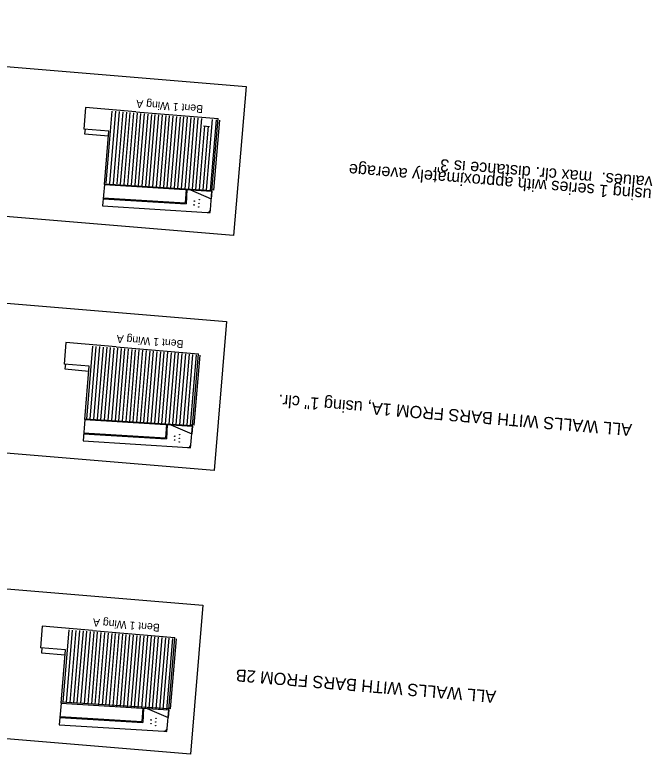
# Model space of a CAD drawing. Extents: x 1313815 to 1314857, y 2089008 to 2089414.
# Drawn here: x 1314659 to 1314747.7, y 2089292.2 to 2089395.1 of the extents above; entities that cross this region are included whole.
import ezdxf

# ---------------------------------------------------------------- set-up
doc = ezdxf.new("R2010")
doc.units = 0
for name, color, linetype in [('B-Gen-Construction Line', 7, 'Continuous'), ('B-Gen-Hidden', 7, 'Continuous'), ('B-Gen-Rebar', 7, 'Continuous'), ('B-Gen-Viewport', 7, 'Continuous'), ('B-Sub-Abutment Cap (Hidden)', 7, 'Continuous'), ('B-Sub-Wingwall', 7, 'Continuous'), ('B-Super-Parapet', 7, 'Continuous')]:
    doc.layers.add(name, color=color, linetype=linetype)

msp = doc.modelspace()

# ---------------------------------------------------------------- linework, layer by layer
at = {"layer": 'B-Gen-Construction Line'}
msp.add_line((1314685.25, 2089379.66), (1314686.06, 2089379.59), dxfattribs=at)
at = {"layer": 'B-Gen-Hidden'}
for p, q in [((1314686.69, 2089370.71), (1314687.5, 2089380.47)), ((1314671.45, 2089371.5), (1314686.42, 2089370.57)), ((1314671.46, 2089371.58), (1314686.43, 2089370.65)), ((1314682.81, 2089370.8), (1314682.69, 2089368.93)), ((1314682.93, 2089370.79), (1314682.81, 2089368.79)), ((1314683.43, 2089370.76), (1314686.33, 2089369.49)), ((1314686.69, 2089370.71), (1314686.19, 2089370.75)), ((1314671.28, 2089369.51), (1314682.81, 2089368.79)), ((1314671.29, 2089369.63), (1314682.69, 2089368.93)), ((1314686.17, 2089367.58), (1314686.21, 2089367.99)), ((1314685.77, 2089367.61), (1314686.17, 2089367.58)), ((1314683.96, 2089338), (1314684.77, 2089347.76)), ((1314668.72, 2089338.79), (1314683.69, 2089337.86)), ((1314668.73, 2089338.87), (1314683.7, 2089337.95)), ((1314680.08, 2089338.09), (1314679.96, 2089336.22)), ((1314680.2, 2089338.08), (1314680.08, 2089336.08)), ((1314680.7, 2089338.05), (1314683.6, 2089336.78)), ((1314683.96, 2089338), (1314683.46, 2089338.04)), ((1314668.56, 2089336.92), (1314679.96, 2089336.22)), ((1314668.55, 2089336.8), (1314680.08, 2089336.08)), ((1314683.04, 2089334.9), (1314683.44, 2089334.87)), ((1314683.44, 2089334.87), (1314683.48, 2089335.28)), ((1314680.66, 2089298.52), (1314681.48, 2089308.28)), ((1314665.42, 2089299.31), (1314680.4, 2089298.38)), ((1314665.44, 2089299.48), (1314680.41, 2089298.55)), ((1314676.78, 2089298.61), (1314676.66, 2089296.74)), ((1314676.9, 2089298.6), (1314676.78, 2089296.61)), ((1314677.4, 2089298.57), (1314680.31, 2089297.3)), ((1314680.66, 2089298.52), (1314680.16, 2089298.57)), ((1314665.26, 2089297.32), (1314676.78, 2089296.61)), ((1314665.27, 2089297.44), (1314676.66, 2089296.74)), ((1314680.15, 2089295.39), (1314680.18, 2089295.8)), ((1314679.74, 2089295.42), (1314680.15, 2089295.39))]:
    msp.add_line(p, q, dxfattribs=at)
at = {"layer": 'B-Gen-Rebar'}
for p, q in [((1314671.71, 2089371.67), (1314672.55, 2089381.72)), ((1314672.21, 2089371.64), (1314673.05, 2089381.68)), ((1314672.71, 2089371.6), (1314673.55, 2089381.64)), ((1314673.21, 2089371.57), (1314674.05, 2089381.59)), ((1314673.71, 2089371.53), (1314674.55, 2089381.55)), ((1314674.21, 2089371.5), (1314675.05, 2089381.51)), ((1314674.71, 2089371.46), (1314675.54, 2089381.47)), ((1314675.21, 2089371.43), (1314676.04, 2089381.43)), ((1314675.71, 2089371.39), (1314676.54, 2089381.39)), ((1314676.2, 2089371.36), (1314677.04, 2089381.34)), ((1314676.7, 2089371.33), (1314677.54, 2089381.3)), ((1314677.2, 2089371.29), (1314678.03, 2089381.26)), ((1314677.7, 2089371.26), (1314678.53, 2089381.22)), ((1314678.2, 2089371.22), (1314679.03, 2089381.18)), ((1314678.7, 2089371.19), (1314679.53, 2089381.14)), ((1314679.2, 2089371.15), (1314680.03, 2089381.09)), ((1314679.7, 2089371.12), (1314680.53, 2089381.05)), ((1314680.2, 2089371.08), (1314681.02, 2089381.01)), ((1314680.69, 2089371.05), (1314681.52, 2089380.97)), ((1314681.19, 2089371.02), (1314682.02, 2089380.93)), ((1314681.69, 2089370.98), (1314682.52, 2089380.89)), ((1314682.19, 2089370.95), (1314683.02, 2089380.85)), ((1314682.69, 2089370.91), (1314683.52, 2089380.8)), ((1314683.19, 2089370.88), (1314684.01, 2089380.76)), ((1314683.69, 2089370.84), (1314684.51, 2089380.72)), ((1314684.19, 2089370.81), (1314685.01, 2089380.68)), ((1314685.68, 2089370.71), (1314686.51, 2089380.55)), ((1314687, 2089380.51), (1314686.18, 2089370.67)), ((1314684.69, 2089370.77), (1314685.43, 2089379.64)), ((1314685.18, 2089370.74), (1314685.92, 2089379.6)), ((1314668.98, 2089338.86), (1314669.82, 2089349.01)), ((1314669.48, 2089338.83), (1314670.32, 2089348.97)), ((1314669.97, 2089338.8), (1314670.82, 2089348.93)), ((1314670.47, 2089338.77), (1314671.32, 2089348.88)), ((1314670.97, 2089338.74), (1314671.82, 2089348.84)), ((1314671.47, 2089338.7), (1314672.31, 2089348.8)), ((1314671.97, 2089338.67), (1314672.81, 2089348.76)), ((1314672.47, 2089338.64), (1314673.31, 2089348.72)), ((1314672.97, 2089338.61), (1314673.81, 2089348.68)), ((1314673.47, 2089338.58), (1314674.31, 2089348.63)), ((1314673.97, 2089338.55), (1314674.81, 2089348.59)), ((1314674.47, 2089338.52), (1314675.3, 2089348.55)), ((1314674.97, 2089338.49), (1314675.8, 2089348.51)), ((1314675.47, 2089338.46), (1314676.3, 2089348.47)), ((1314675.96, 2089338.43), (1314676.8, 2089348.43)), ((1314676.46, 2089338.39), (1314677.3, 2089348.39)), ((1314676.96, 2089338.36), (1314677.8, 2089348.34)), ((1314677.46, 2089338.33), (1314678.29, 2089348.3)), ((1314677.96, 2089338.3), (1314678.79, 2089348.26)), ((1314678.46, 2089338.27), (1314679.29, 2089348.22)), ((1314678.96, 2089338.24), (1314679.79, 2089348.18)), ((1314679.46, 2089338.21), (1314680.29, 2089348.14)), ((1314679.96, 2089338.18), (1314680.79, 2089348.09)), ((1314680.46, 2089338.15), (1314681.28, 2089348.05)), ((1314680.96, 2089338.12), (1314681.78, 2089348.01)), ((1314681.45, 2089338.09), (1314682.28, 2089347.97)), ((1314681.95, 2089338.05), (1314682.78, 2089347.93)), ((1314682.45, 2089338.02), (1314683.28, 2089347.89)), ((1314682.95, 2089337.99), (1314683.77, 2089347.84)), ((1314683.45, 2089337.96), (1314684.27, 2089347.8)), ((1314665.69, 2089299.46), (1314666.53, 2089309.53)), ((1314666.19, 2089299.42), (1314667.03, 2089309.49)), ((1314666.68, 2089299.39), (1314667.52, 2089309.45)), ((1314667.18, 2089299.35), (1314668.02, 2089309.41)), ((1314667.68, 2089299.32), (1314668.52, 2089309.36)), ((1314668.18, 2089299.28), (1314669.02, 2089309.32)), ((1314668.68, 2089299.24), (1314669.52, 2089309.28)), ((1314669.18, 2089299.21), (1314670.02, 2089309.24)), ((1314669.68, 2089299.17), (1314670.51, 2089309.2)), ((1314670.18, 2089299.13), (1314671.01, 2089309.16)), ((1314670.67, 2089299.1), (1314671.51, 2089309.12)), ((1314671.17, 2089299.06), (1314672.01, 2089309.07)), ((1314671.67, 2089299.02), (1314672.51, 2089309.03)), ((1314672.17, 2089298.99), (1314673.01, 2089308.99)), ((1314672.67, 2089298.95), (1314673.5, 2089308.95)), ((1314673.17, 2089298.91), (1314674, 2089308.91)), ((1314673.67, 2089298.88), (1314674.5, 2089308.87)), ((1314674.17, 2089298.84), (1314675, 2089308.82)), ((1314674.66, 2089298.8), (1314675.5, 2089308.78)), ((1314675.16, 2089298.77), (1314676, 2089308.74)), ((1314675.66, 2089298.73), (1314676.49, 2089308.7)), ((1314676.16, 2089298.7), (1314676.99, 2089308.66)), ((1314676.66, 2089298.66), (1314677.49, 2089308.62)), ((1314677.16, 2089298.62), (1314677.99, 2089308.57)), ((1314677.66, 2089298.59), (1314678.49, 2089308.53)), ((1314678.15, 2089298.55), (1314678.98, 2089308.49)), ((1314678.65, 2089298.51), (1314679.48, 2089308.45)), ((1314679.15, 2089298.48), (1314679.98, 2089308.41)), ((1314679.65, 2089298.44), (1314680.48, 2089308.37)), ((1314680.15, 2089298.4), (1314680.98, 2089308.32))]:
    msp.add_line(p, q, dxfattribs=at)
for centre, radius in [((1314683.97, 2089369.18), 0.0313), ((1314684.62, 2089368.88), 0.0313), ((1314684.66, 2089369.4), 0.0312), ((1314683.94, 2089368.66), 0.0313), ((1314684.59, 2089368.35), 0.0313), ((1314681.21, 2089335.95), 0.0313), ((1314681.24, 2089336.47), 0.0313), ((1314681.89, 2089336.17), 0.0313), ((1314681.93, 2089336.69), 0.0312), ((1314681.86, 2089335.65), 0.0313), ((1314677.95, 2089296.99), 0.0313), ((1314678.63, 2089297.21), 0.0312), ((1314677.92, 2089296.47), 0.0313), ((1314678.57, 2089296.17), 0.0313), ((1314678.6, 2089296.69), 0.0313)]:
    msp.add_circle(centre, radius, dxfattribs=at)
at = {"layer": 'B-Gen-Viewport'}
for points in [[(1314689.44, 2089364.4), (1314569.73, 2089374.39), (1314571.46, 2089395.11), (1314691.17, 2089385.12)], [(1314686.71, 2089331.69), (1314567, 2089341.68), (1314568.73, 2089362.41), (1314688.44, 2089352.41)], [(1314683.41, 2089292.21), (1314563.7, 2089302.2), (1314565.43, 2089322.93), (1314685.14, 2089312.93)]]:
    msp.add_lwpolyline(points, close=True, dxfattribs=at)
at = {"layer": 'B-Sub-Wingwall'}
for p, q in [((1314668.83, 2089382.2), (1314668.58, 2089379.21)), ((1314675.81, 2089381.61), (1314668.83, 2089382.2)), ((1314675.81, 2089381.61), (1314687.27, 2089380.66)), ((1314686.42, 2089370.57), (1314687.27, 2089380.66)), ((1314672.07, 2089378.92), (1314668.58, 2089379.21)), ((1314668.75, 2089379.19), (1314668.69, 2089378.53)), ((1314668.69, 2089378.53), (1314672.01, 2089378.25)), ((1314671.45, 2089371.5), (1314672.07, 2089378.92)), ((1314666.1, 2089349.49), (1314665.85, 2089346.5)), ((1314673.08, 2089348.9), (1314666.1, 2089349.49)), ((1314673.08, 2089348.9), (1314684.54, 2089347.95)), ((1314683.69, 2089337.86), (1314684.54, 2089347.95)), ((1314669.34, 2089346.21), (1314665.85, 2089346.5)), ((1314666.02, 2089346.48), (1314665.96, 2089345.82)), ((1314668.72, 2089338.79), (1314669.34, 2089346.21)), ((1314665.96, 2089345.82), (1314669.28, 2089345.54)), ((1314662.8, 2089310.01), (1314662.56, 2089307.02)), ((1314669.78, 2089309.43), (1314662.8, 2089310.01)), ((1314669.78, 2089309.43), (1314681.24, 2089308.47)), ((1314680.4, 2089298.38), (1314681.24, 2089308.47)), ((1314666.04, 2089306.73), (1314662.56, 2089307.02)), ((1314662.72, 2089307.01), (1314662.67, 2089306.34)), ((1314662.67, 2089306.34), (1314665.99, 2089306.06)), ((1314665.42, 2089299.31), (1314666.04, 2089306.73))]:
    msp.add_line(p, q, dxfattribs=at)
for centre in [(1314685.79, 2089368.02), (1314683.06, 2089335.31), (1314679.77, 2089295.84)]:
    msp.add_arc(centre, 0.417, 266.1099, 355.2284, dxfattribs=at)
at = {"layer": 'B-Super-Parapet'}
for p, q in [((1314671.45, 2089371.5), (1314671.2, 2089368.51)), ((1314686.21, 2089367.99), (1314686.42, 2089370.57)), ((1314686.42, 2089370.57), (1314686.33, 2089369.49)), ((1314671.2, 2089368.51), (1314685.77, 2089367.61)), ((1314668.72, 2089338.79), (1314668.47, 2089335.8)), ((1314683.48, 2089335.28), (1314683.69, 2089337.86)), ((1314683.69, 2089337.86), (1314683.6, 2089336.78)), ((1314668.47, 2089335.8), (1314683.04, 2089334.9)), ((1314665.42, 2089299.31), (1314665.17, 2089296.32)), ((1314680.18, 2089295.8), (1314680.4, 2089298.38)), ((1314680.4, 2089298.38), (1314680.31, 2089297.3)), ((1314665.17, 2089296.32), (1314679.74, 2089295.42))]:
    msp.add_line(p, q, dxfattribs=at)

# ---------------------------------------------------------------- texts
at = {"layer": 'B-Gen-Construction Line'}
for s, p in [('values.  max clr. distance is 3"', (1314747.82, 2089372.58)), ('using 1 series with approximately average ', (1314747.67, 2089370.88)), ('ALL WALLS WITH BARS FROM 1A, using 1" clr.', (1314744.94, 2089338.17)), ('ALL WALLS WITH BARS FROM 2B', (1314726.02, 2089301.03))]:
    msp.add_text(s, height=1.6984, rotation=175.2284, dxfattribs=at).set_placement(p)
at = {"layer": 'B-Sub-Abutment Cap (Hidden)'}
for p in [(1314685.22, 2089382.51), (1314682.49, 2089349.8), (1314679.19, 2089310.33)]:
    msp.add_text('Bent 1 Wing A', height=1.0911, rotation=175.2284, dxfattribs=at).set_placement(p)

doc.saveas('drawing.dxf')
